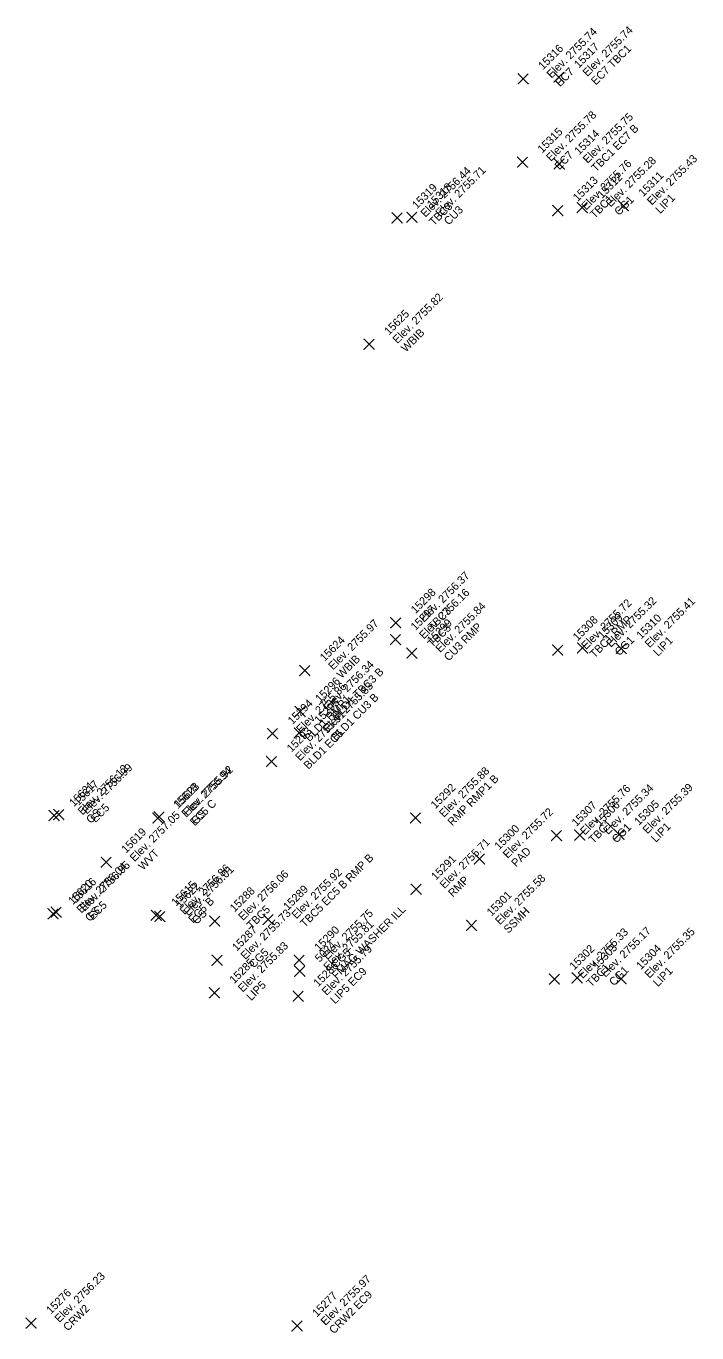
# Model space of a CAD drawing. Extents: x 2493999 to 2503109, y 700767 to 706646.
# Drawn here: x 2502243.86 to 2502263.99, y 703542.16 to 703581.36 of the extents above; entities that cross this region are included whole.
import ezdxf

# ---------------------------------------------------------------- set-up
doc = ezdxf.new("R2010")
doc.units = 0
doc.layers.add('ALG_CL_BLUE_Horiz', color=7, linetype='Continuous')
doc.layers.add('DES_SURFACE_Existing-Ground', color=7, linetype='Continuous')

msp = doc.modelspace()

# ---------------------------------------------------------------- linework, layer by layer
at = {"layer": 'ALG_CL_BLUE_Horiz'}
for points in [[(2502259.849, 703579.832), (2502259.699, 703579.982), (2502259.849, 703579.832), (2502259.699, 703579.682), (2502259.849, 703579.832), (2502259.999, 703579.682), (2502259.849, 703579.832), (2502259.999, 703579.982)], [(2502258.776, 703579.782), (2502258.626, 703579.932), (2502258.776, 703579.782), (2502258.626, 703579.632), (2502258.776, 703579.782), (2502258.926, 703579.632), (2502258.776, 703579.782), (2502258.926, 703579.932)], [(2502258.755, 703577.285), (2502258.605, 703577.435), (2502258.755, 703577.285), (2502258.605, 703577.135), (2502258.755, 703577.285), (2502258.905, 703577.135), (2502258.755, 703577.285), (2502258.905, 703577.435)], [(2502259.859, 703577.227), (2502259.709, 703577.377), (2502259.859, 703577.227), (2502259.709, 703577.077), (2502259.859, 703577.227), (2502260.009, 703577.077), (2502259.859, 703577.227), (2502260.009, 703577.377)], [(2502260.548, 703575.918), (2502260.398, 703576.068), (2502260.548, 703575.918), (2502260.398, 703575.768), (2502260.548, 703575.918), (2502260.698, 703575.768), (2502260.548, 703575.918), (2502260.698, 703576.068)], [(2502261.782, 703575.975), (2502261.632, 703576.125), (2502261.782, 703575.975), (2502261.632, 703575.825), (2502261.782, 703575.975), (2502261.932, 703575.825), (2502261.782, 703575.975), (2502261.932, 703576.125)], [(2502254.991, 703575.609), (2502254.841, 703575.759), (2502254.991, 703575.609), (2502254.841, 703575.459), (2502254.991, 703575.609), (2502255.141, 703575.459), (2502254.991, 703575.609), (2502255.141, 703575.759)], [(2502255.436, 703575.63), (2502255.286, 703575.78), (2502255.436, 703575.63), (2502255.286, 703575.48), (2502255.436, 703575.63), (2502255.586, 703575.48), (2502255.436, 703575.63), (2502255.586, 703575.78)], [(2502259.814, 703575.828), (2502259.664, 703575.978), (2502259.814, 703575.828), (2502259.664, 703575.678), (2502259.814, 703575.828), (2502259.964, 703575.678), (2502259.814, 703575.828), (2502259.964, 703575.978)], [(2502254.154, 703571.82), (2502254.004, 703571.97), (2502254.154, 703571.82), (2502254.004, 703571.67), (2502254.154, 703571.82), (2502254.304, 703571.67), (2502254.154, 703571.82), (2502254.304, 703571.97)], [(2502254.951, 703563.466), (2502254.801, 703563.616), (2502254.951, 703563.466), (2502254.801, 703563.316), (2502254.951, 703563.466), (2502255.101, 703563.316), (2502254.951, 703563.466), (2502255.101, 703563.616)], [(2502254.949, 703562.958), (2502254.799, 703563.108), (2502254.949, 703562.958), (2502254.799, 703562.808), (2502254.949, 703562.958), (2502255.099, 703562.808), (2502254.949, 703562.958), (2502255.099, 703563.108)], [(2502255.436, 703562.552), (2502255.286, 703562.702), (2502255.436, 703562.552), (2502255.286, 703562.402), (2502255.436, 703562.552), (2502255.586, 703562.402), (2502255.436, 703562.552), (2502255.586, 703562.702)], [(2502259.811, 703562.644), (2502259.661, 703562.794), (2502259.811, 703562.644), (2502259.661, 703562.494), (2502259.811, 703562.644), (2502259.961, 703562.494), (2502259.811, 703562.644), (2502259.961, 703562.794)], [(2502260.559, 703562.71), (2502260.409, 703562.86), (2502260.559, 703562.71), (2502260.409, 703562.56), (2502260.559, 703562.71), (2502260.709, 703562.56), (2502260.559, 703562.71), (2502260.709, 703562.86)], [(2502261.719, 703562.696), (2502261.569, 703562.846), (2502261.719, 703562.696), (2502261.569, 703562.546), (2502261.719, 703562.696), (2502261.869, 703562.546), (2502261.719, 703562.696), (2502261.869, 703562.846)], [(2502252.223, 703562.031), (2502252.073, 703562.181), (2502252.223, 703562.031), (2502252.073, 703561.881), (2502252.223, 703562.031), (2502252.373, 703561.881), (2502252.223, 703562.031), (2502252.373, 703562.181)], [(2502252.083, 703560.801), (2502251.933, 703560.951), (2502252.083, 703560.801), (2502251.933, 703560.651), (2502252.083, 703560.801), (2502252.233, 703560.651), (2502252.083, 703560.801), (2502252.233, 703560.951)], [(2502251.259, 703560.137), (2502251.109, 703560.287), (2502251.259, 703560.137), (2502251.109, 703559.987), (2502251.259, 703560.137), (2502251.409, 703559.987), (2502251.259, 703560.137), (2502251.409, 703560.287)], [(2502252.059, 703560.159), (2502251.909, 703560.309), (2502252.059, 703560.159), (2502251.909, 703560.009), (2502252.059, 703560.159), (2502252.209, 703560.009), (2502252.059, 703560.159), (2502252.209, 703560.309)], [(2502251.229, 703559.305), (2502251.079, 703559.455), (2502251.229, 703559.305), (2502251.079, 703559.155), (2502251.229, 703559.305), (2502251.379, 703559.155), (2502251.229, 703559.305), (2502251.379, 703559.455)], [(2502244.704, 703557.678), (2502244.554, 703557.828), (2502244.704, 703557.678), (2502244.554, 703557.528), (2502244.704, 703557.678), (2502244.854, 703557.528), (2502244.704, 703557.678), (2502244.854, 703557.828)], [(2502244.84, 703557.707), (2502244.69, 703557.857), (2502244.84, 703557.707), (2502244.69, 703557.557), (2502244.84, 703557.707), (2502244.99, 703557.557), (2502244.84, 703557.707), (2502244.99, 703557.857)], [(2502247.819, 703557.606), (2502247.669, 703557.756), (2502247.819, 703557.606), (2502247.669, 703557.456), (2502247.819, 703557.606), (2502247.969, 703557.456), (2502247.819, 703557.606), (2502247.969, 703557.756)], [(2502247.857, 703557.645), (2502247.707, 703557.795), (2502247.857, 703557.645), (2502247.707, 703557.495), (2502247.857, 703557.645), (2502248.007, 703557.495), (2502247.857, 703557.645), (2502248.007, 703557.795)], [(2502255.546, 703557.609), (2502255.396, 703557.759), (2502255.546, 703557.609), (2502255.396, 703557.459), (2502255.546, 703557.609), (2502255.696, 703557.459), (2502255.546, 703557.609), (2502255.696, 703557.759)], [(2502259.777, 703557.08), (2502259.627, 703557.23), (2502259.777, 703557.08), (2502259.627, 703556.93), (2502259.777, 703557.08), (2502259.927, 703556.93), (2502259.777, 703557.08), (2502259.927, 703557.23)], [(2502260.471, 703557.092), (2502260.321, 703557.242), (2502260.471, 703557.092), (2502260.321, 703556.942), (2502260.471, 703557.092), (2502260.621, 703556.942), (2502260.471, 703557.092), (2502260.621, 703557.242)], [(2502261.653, 703557.113), (2502261.503, 703557.263), (2502261.653, 703557.113), (2502261.503, 703556.963), (2502261.653, 703557.113), (2502261.803, 703556.963), (2502261.653, 703557.113), (2502261.803, 703557.263)], [(2502246.266, 703556.28), (2502246.116, 703556.43), (2502246.266, 703556.28), (2502246.116, 703556.13), (2502246.266, 703556.28), (2502246.416, 703556.13), (2502246.266, 703556.28), (2502246.416, 703556.43)], [(2502257.46, 703556.378), (2502257.31, 703556.528), (2502257.46, 703556.378), (2502257.31, 703556.228), (2502257.46, 703556.378), (2502257.61, 703556.228), (2502257.46, 703556.378), (2502257.61, 703556.528)], [(2502255.563, 703555.47), (2502255.413, 703555.62), (2502255.563, 703555.47), (2502255.413, 703555.32), (2502255.563, 703555.47), (2502255.713, 703555.32), (2502255.563, 703555.47), (2502255.713, 703555.62)], [(2502244.672, 703554.734), (2502244.522, 703554.884), (2502244.672, 703554.734), (2502244.522, 703554.584), (2502244.672, 703554.734), (2502244.822, 703554.584), (2502244.672, 703554.734), (2502244.822, 703554.884)], [(2502244.767, 703554.784), (2502244.617, 703554.934), (2502244.767, 703554.784), (2502244.617, 703554.634), (2502244.767, 703554.784), (2502244.917, 703554.634), (2502244.767, 703554.784), (2502244.917, 703554.934)], [(2502247.768, 703554.689), (2502247.618, 703554.839), (2502247.768, 703554.689), (2502247.618, 703554.539), (2502247.768, 703554.689), (2502247.918, 703554.539), (2502247.768, 703554.689), (2502247.918, 703554.839)], [(2502247.878, 703554.653), (2502247.728, 703554.803), (2502247.878, 703554.653), (2502247.728, 703554.503), (2502247.878, 703554.653), (2502248.028, 703554.503), (2502247.878, 703554.653), (2502248.028, 703554.803)], [(2502249.523, 703554.513), (2502249.373, 703554.663), (2502249.523, 703554.513), (2502249.373, 703554.363), (2502249.523, 703554.513), (2502249.673, 703554.363), (2502249.523, 703554.513), (2502249.673, 703554.663)], [(2502251.123, 703554.564), (2502250.973, 703554.714), (2502251.123, 703554.564), (2502250.973, 703554.414), (2502251.123, 703554.564), (2502251.273, 703554.414), (2502251.123, 703554.564), (2502251.273, 703554.714)], [(2502257.229, 703554.387), (2502257.079, 703554.537), (2502257.229, 703554.387), (2502257.079, 703554.237), (2502257.229, 703554.387), (2502257.379, 703554.237), (2502257.229, 703554.387), (2502257.379, 703554.537)], [(2502249.591, 703553.342), (2502249.441, 703553.492), (2502249.591, 703553.342), (2502249.441, 703553.192), (2502249.591, 703553.342), (2502249.741, 703553.192), (2502249.591, 703553.342), (2502249.741, 703553.492)], [(2502252.057, 703553.338), (2502251.907, 703553.488), (2502252.057, 703553.338), (2502251.907, 703553.188), (2502252.057, 703553.338), (2502252.207, 703553.188), (2502252.057, 703553.338), (2502252.207, 703553.488)], [(2502252.074, 703553.009), (2502251.924, 703553.159), (2502252.074, 703553.009), (2502251.924, 703552.859), (2502252.074, 703553.009), (2502252.224, 703552.859), (2502252.074, 703553.009), (2502252.224, 703553.159)], [(2502259.71, 703552.775), (2502259.56, 703552.925), (2502259.71, 703552.775), (2502259.56, 703552.625), (2502259.71, 703552.775), (2502259.86, 703552.625), (2502259.71, 703552.775), (2502259.86, 703552.925)], [(2502260.392, 703552.809), (2502260.242, 703552.959), (2502260.392, 703552.809), (2502260.242, 703552.659), (2502260.392, 703552.809), (2502260.542, 703552.659), (2502260.392, 703552.809), (2502260.542, 703552.959)], [(2502261.711, 703552.786), (2502261.561, 703552.936), (2502261.711, 703552.786), (2502261.561, 703552.636), (2502261.711, 703552.786), (2502261.861, 703552.636), (2502261.711, 703552.786), (2502261.861, 703552.936)], [(2502249.511, 703552.363), (2502249.361, 703552.513), (2502249.511, 703552.363), (2502249.361, 703552.213), (2502249.511, 703552.363), (2502249.661, 703552.213), (2502249.511, 703552.363), (2502249.661, 703552.513)], [(2502252.029, 703552.267), (2502251.879, 703552.417), (2502252.029, 703552.267), (2502251.879, 703552.117), (2502252.029, 703552.267), (2502252.179, 703552.117), (2502252.029, 703552.267), (2502252.179, 703552.417)], [(2502244.014, 703542.454), (2502243.864, 703542.604), (2502244.014, 703542.454), (2502243.864, 703542.304), (2502244.014, 703542.454), (2502244.164, 703542.304), (2502244.014, 703542.454), (2502244.164, 703542.604)], [(2502251.993, 703542.368), (2502251.843, 703542.518), (2502251.993, 703542.368), (2502251.843, 703542.218), (2502251.993, 703542.368), (2502252.143, 703542.218), (2502251.993, 703542.368), (2502252.143, 703542.518)]]:
    msp.add_lwpolyline(points, dxfattribs=at)

# ---------------------------------------------------------------- texts
at = {"layer": 'DES_SURFACE_Existing-Ground'}
for s, p in [('Elev. 2755.74', (2502259.625, 703579.782)), ('Elev. 2755.74', (2502260.698, 703579.832)), ('15316', (2502259.37, 703580.037)), ('15317', (2502260.443, 703580.087)), ('EC7 TBC1', (2502260.952, 703579.577)), ('EC7', (2502259.879, 703579.527)), ('Elev. 2755.78', (2502259.604, 703577.285)), ('Elev. 2755.75', (2502260.708, 703577.227)), ('TBC1 EC7 B', (2502260.962, 703576.972)), ('15315', (2502259.349, 703577.54)), ('15314', (2502260.453, 703577.482)), ('EC7', (2502259.858, 703577.03)), ('Elev. 2755.76', (2502260.663, 703575.828)), ('Elev. 2755.28', (2502261.397, 703575.918)), ('Elev. 2755.43', (2502262.631, 703575.975)), ('Elev. 2756.44', (2502255.84, 703575.609)), ('Elev. 2755.71', (2502256.285, 703575.63)), ('15313', (2502260.408, 703576.083)), ('15312', (2502261.142, 703576.173)), ('15311', (2502262.376, 703576.23)), ('15319', (2502255.585, 703575.864)), ('15318', (2502256.03, 703575.885)), ('TBC3', (2502256.094, 703575.354)), ('TBC1', (2502260.917, 703575.573)), ('CG1', (2502261.651, 703575.663)), ('LIP1', (2502262.885, 703575.72)), ('CU3', (2502256.539, 703575.375)), ('Elev. 2755.82', (2502255.003, 703571.82)), ('15625', (2502254.748, 703572.075)), ('WBIB', (2502255.257, 703571.565)), ('Elev. 2756.37', (2502255.8, 703563.466)), ('15298', (2502255.545, 703563.721)), ('Elev. 2756.16', (2502255.798, 703562.958)), ('15297', (2502255.543, 703563.213)), ('TBC3', (2502256.054, 703563.211)), ('Elev. 2755.84', (2502256.285, 703562.552)), ('Elev. 2755.72', (2502260.66, 703562.644)), ('Elev. 2755.32', (2502261.408, 703562.71)), ('Elev. 2755.41', (2502262.568, 703562.696)), ('Elev. 2755.97', (2502253.072, 703562.031)), ('15299', (2502256.03, 703562.807)), ('15308', (2502260.405, 703562.899)), ('TBC1 RMP', (2502260.914, 703562.389)), ('15309', (2502261.153, 703562.965)), ('15310', (2502262.313, 703562.951)), ('TBC3', (2502256.052, 703562.703)), ('CU3 RMP', (2502256.539, 703562.297)), ('15624', (2502252.817, 703562.286)), ('CG1', (2502261.662, 703562.455)), ('LIP1', (2502262.822, 703562.441)), ('Elev. 2756.34', (2502252.932, 703560.801)), ('WBIB', (2502253.326, 703561.776)), ('BLD1 TBC3 B', (2502253.186, 703560.546)), ('Elev. 2755.86', (2502252.108, 703560.137)), ('15296', (2502252.677, 703561.056)), ('Elev. 2755.83', (2502252.908, 703560.159)), ('15294', (2502251.853, 703560.392)), ('BLD1 RMP1', (2502252.362, 703559.882)), ('15295', (2502252.653, 703560.414)), ('BLD1 CU3 B', (2502253.162, 703559.904)), ('Elev. 2755.91', (2502252.078, 703559.305)), ('15293', (2502251.823, 703559.56)), ('BLD1 EC5', (2502252.332, 703559.05)), ('Elev. 2756.12', (2502245.553, 703557.678)), ('Elev. 2756.99', (2502245.689, 703557.707)), ('Elev. 2756.94', (2502248.668, 703557.606)), ('Elev. 2755.92', (2502248.706, 703557.645)), ('Elev. 2755.88', (2502256.395, 703557.609)), ('RMP RMP1 B', (2502256.649, 703557.354)), ('15621', (2502245.298, 703557.933)), ('15617', (2502245.434, 703557.962)), ('15618', (2502248.413, 703557.861)), ('15623', (2502248.451, 703557.9)), ('15292', (2502256.14, 703557.864)), ('Elev. 2755.76', (2502260.626, 703557.08)), ('Elev. 2755.34', (2502261.32, 703557.092)), ('Elev. 2755.39', (2502262.502, 703557.113)), ('EC5', (2502245.943, 703557.452)), ('EC5 C', (2502248.922, 703557.351)), ('15307', (2502260.371, 703557.335)), ('15306', (2502261.065, 703557.347)), ('15305', (2502262.247, 703557.368)), ('GS', (2502245.807, 703557.423)), ('Elev. 2757.05', (2502247.115, 703556.28)), ('GS', (2502248.96, 703557.39)), ('Elev. 2755.72', (2502258.309, 703556.378)), ('15619', (2502246.86, 703556.535)), ('15300', (2502258.054, 703556.633)), ('TBC1', (2502260.88, 703556.825)), ('CG1', (2502261.574, 703556.837)), ('LIP1', (2502262.756, 703556.858)), ('Elev. 2755.71', (2502256.412, 703555.47)), ('WVT', (2502247.369, 703556.025)), ('TBC5 EC5 B RMP B', (2502252.226, 703554.309)), ('15291', (2502256.157, 703555.725)), ('PAD', (2502258.563, 703556.123)), ('Elev. 2756.04', (2502245.521, 703554.734)), ('Elev. 2756.95', (2502245.616, 703554.784)), ('Elev. 2756.86', (2502248.617, 703554.689)), ('Elev. 2756.01', (2502248.727, 703554.653)), ('Elev. 2756.06', (2502250.372, 703554.513)), ('Elev. 2755.92', (2502251.972, 703554.564)), ('15620', (2502245.266, 703554.989)), ('15616', (2502245.361, 703555.039)), ('15615', (2502248.362, 703554.944)), ('15622', (2502248.472, 703554.908)), ('RMP', (2502256.666, 703555.215)), ('Elev. 2755.58', (2502258.078, 703554.387)), ('15288', (2502250.117, 703554.768)), ('15289', (2502251.717, 703554.819)), ('15301', (2502257.823, 703554.642)), ('GS', (2502245.775, 703554.479)), ('EC5', (2502245.87, 703554.529)), ('EC5 B', (2502248.871, 703554.434)), ('GS', (2502248.981, 703554.398)), ('Elev. 2755.73', (2502250.44, 703553.342)), ('TBC5', (2502250.626, 703554.258)), ('Elev. 2755.75', (2502252.906, 703553.338)), ('FMAG WASHER ILL', (2502253.177, 703552.754)), ('SSMH', (2502258.332, 703554.132)), ('Elev. 2755.81', (2502252.923, 703553.009)), ('15287', (2502250.185, 703553.597)), ('15290', (2502252.651, 703553.593)), ('Elev. 2755.33', (2502260.559, 703552.775)), ('Elev. 2755.17', (2502261.241, 703552.809)), ('Elev. 2755.35', (2502262.56, 703552.786)), ('Elev. 2755.83', (2502250.36, 703552.363)), ('CG5', (2502250.694, 703553.087)), ('5024', (2502252.668, 703553.264)), ('Elev. 2755.79', (2502252.878, 703552.267)), ('CG5', (2502253.16, 703553.083)), ('15302', (2502260.304, 703553.03)), ('15303', (2502260.986, 703553.064)), ('15304', (2502262.305, 703553.041)), ('15285', (2502250.105, 703552.618)), ('15286', (2502252.623, 703552.522)), ('LIP5 EC9', (2502253.132, 703552.012)), ('TBC1', (2502260.813, 703552.52)), ('CG1', (2502261.495, 703552.554)), ('LIP1', (2502262.814, 703552.531)), ('LIP5', (2502250.614, 703552.108)), ('Elev. 2756.23', (2502244.863, 703542.454)), ('Elev. 2755.97', (2502252.842, 703542.368)), ('15276', (2502244.608, 703542.709)), ('15277', (2502252.587, 703542.623)), ('CRW2 EC9', (2502253.096, 703542.113)), ('CRW2', (2502245.117, 703542.199))]:
    msp.add_text(s, height=0.24, rotation=45, dxfattribs=at).set_placement(p)

doc.saveas('drawing.dxf')
